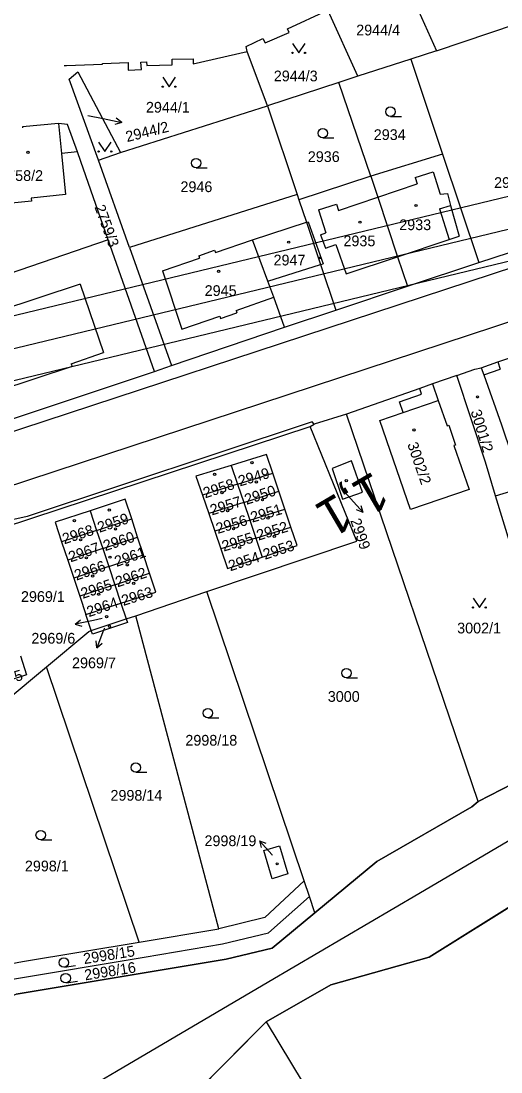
# Model space of a CAD drawing. Extents: x -738085 to -734306, y -1122197 to -1119753.
# Drawn here: x -735134.3 to -735058.2, y -1120249.4 to -1120082.8 of the extents above; entities that cross this region are included whole.
import ezdxf

# ---------------------------------------------------------------- set-up
doc = ezdxf.new("R2010")
doc.units = 0
for name, color, linetype in [('Hranice parcel', 7, 'Continuous'), ('Parcelní čísla', 7, 'Continuous'), ('Pop  PČ popisy', 7, 'Continuous'), ('SŽDC', 7, 'Continuous'), ('Vnitřní kresba', 7, 'Continuous'), ('Vrstva 1', 7, 'Continuous'), ('Vrstva 53', 7, 'Continuous'), ('Vrstva 7', 7, 'Continuous'), ('Značky budov', 7, 'Continuous'), ('Značky kultur', 7, 'Continuous')]:
    doc.layers.add(name, color=color, linetype=linetype)

msp = doc.modelspace()

# ---------------------------------------------------------------- linework, layer by layer
at = {"layer": 'Hranice parcel'}
for p, q in [((-735075.3, -1120072.25), (-735068.46, -1120087.54)), ((-735080.9, -1120091.58), (-735085.62, -1120081.24)), ((-735068.46, -1120087.54), (-735055.76, -1120083.29)), ((-735098.45, -1120087.65), (-735098.62, -1120086.89)), ((-735095.23, -1120096.29), (-735098.45, -1120087.65)), ((-735068.46, -1120087.54), (-735072.52, -1120088.87)), ((-735072.52, -1120088.87), (-735080.9, -1120091.58)), ((-735072.52, -1120088.87), (-735067.5, -1120103.92)), ((-735122.01, -1120104.88), (-735126.63, -1120092.04)), ((-735083.9, -1120092.59), (-735095.23, -1120096.29)), ((-735080.9, -1120091.58), (-735083.9, -1120092.59)), ((-735078.86, -1120107.44), (-735083.9, -1120092.59)), ((-735118.5, -1120103.67), (-735095.23, -1120096.29)), ((-735095.23, -1120096.29), (-735090.55, -1120110.32)), ((-735122.01, -1120104.88), (-735118.5, -1120103.67)), ((-735067.5, -1120103.92), (-735078.86, -1120107.44)), ((-735067.5, -1120103.92), (-735061.75, -1120121.13)), ((-735117.09, -1120118.74), (-735122.01, -1120104.88)), ((-735078.86, -1120107.44), (-735090.25, -1120111.21)), ((-735090.55, -1120110.32), (-735117.09, -1120118.74)), ((-735090.55, -1120110.32), (-735090.25, -1120111.21)), ((-735090.25, -1120111.21), (-735089.07, -1120114.75)), ((-735061.75, -1120121.13), (-735045.05, -1120115.6)), ((-735120.46, -1120117.53), (-735145, -1120125.91)), ((-735113.14, -1120138.39), (-735120.46, -1120117.53)), ((-735117.09, -1120118.74), (-735110.45, -1120137.46)), ((-735073.02, -1120124.89), (-735061.75, -1120121.13)), ((-735084.41, -1120128.69), (-735073.02, -1120124.89)), ((-735092.55, -1120131.37), (-735084.41, -1120128.69)), ((-735110.45, -1120137.46), (-735092.55, -1120131.37)), ((-735058.73, -1120136.86), (-735051.05, -1120134.3)), ((-735113.14, -1120138.39), (-735110.45, -1120137.46)), ((-735062.37, -1120138), (-735061.35, -1120137.8)), ((-735061.35, -1120137.8), (-735058.73, -1120136.86)), ((-735061.35, -1120137.8), (-735060.94, -1120138.94)), ((-735065.23, -1120139.01), (-735069.06, -1120140.35)), ((-735065.23, -1120139.01), (-735062.37, -1120138)), ((-735071.11, -1120141.07), (-735082.7, -1120145.17)), ((-735069.06, -1120140.35), (-735071.11, -1120141.07)), ((-735082.7, -1120145.17), (-735087.85, -1120146.72)), ((-735061.82, -1120206.57), (-735082.7, -1120145.17)), ((-735088.44, -1120147.09), (-735087.85, -1120146.72)), ((-735101, -1120153.28), (-735099.98, -1120156.28)), ((-735099.98, -1120156.28), (-735094.37, -1120154.53)), ((-735093.42, -1120157.38), (-735094.37, -1120154.53)), ((-735099.98, -1120156.28), (-735105.53, -1120158.02)), ((-735099.98, -1120156.28), (-735099, -1120159.14)), ((-735099, -1120159.14), (-735093.42, -1120157.38)), ((-735092.47, -1120160.22), (-735093.42, -1120157.38)), ((-735059.09, -1120158.11), (-735054.93, -1120156.86)), ((-735105.53, -1120158.02), (-735104.54, -1120160.89)), ((-735099, -1120159.14), (-735104.54, -1120160.89)), ((-735099, -1120159.14), (-735098.04, -1120161.98)), ((-735046.74, -1120198.74), (-735059.09, -1120158.11)), ((-735123.34, -1120160.47), (-735122.3, -1120163.59)), ((-735104.54, -1120160.89), (-735103.57, -1120163.72)), ((-735098.04, -1120161.98), (-735092.47, -1120160.22)), ((-735091.52, -1120163.05), (-735092.47, -1120160.22)), ((-735122.3, -1120163.59), (-735116.75, -1120161.76)), ((-735115.8, -1120164.64), (-735116.75, -1120161.76)), ((-735098.04, -1120161.98), (-735103.57, -1120163.72)), ((-735098.04, -1120161.98), (-735097.08, -1120164.8)), ((-735122.3, -1120163.59), (-735127.85, -1120165.42)), ((-735122.3, -1120163.59), (-735121.34, -1120166.47)), ((-735103.57, -1120163.72), (-735102.6, -1120166.53)), ((-735097.08, -1120164.8), (-735091.52, -1120163.05)), ((-735127.85, -1120165.42), (-735126.88, -1120168.31)), ((-735121.34, -1120166.47), (-735115.8, -1120164.64)), ((-735114.87, -1120167.48), (-735115.8, -1120164.64)), ((-735097.08, -1120164.8), (-735102.6, -1120166.53)), ((-735097.08, -1120164.8), (-735096.05, -1120167.82)), ((-735121.34, -1120166.47), (-735126.88, -1120168.31)), ((-735121.34, -1120166.47), (-735120.39, -1120169.32)), ((-735120.39, -1120169.32), (-735114.87, -1120167.48)), ((-735113.92, -1120170.36), (-735114.87, -1120167.48)), ((-735126.88, -1120168.31), (-735125.93, -1120171.17)), ((-735120.39, -1120169.32), (-735125.93, -1120171.17)), ((-735120.39, -1120169.32), (-735119.43, -1120172.19)), ((-735119.43, -1120172.19), (-735113.92, -1120170.36)), ((-735125.93, -1120171.17), (-735124.98, -1120174.02)), ((-735119.43, -1120172.19), (-735124.98, -1120174.02)), ((-735119.43, -1120172.19), (-735118.45, -1120175.13)), ((-735124.98, -1120174.02), (-735124.02, -1120176.91)), ((-735116.07, -1120177.1), (-735104.83, -1120173.29)), ((-735089.41, -1120219.11), (-735104.83, -1120173.29)), ((-735124.02, -1120176.91), (-735118.45, -1120175.13)), ((-735118.45, -1120175.13), (-735117.62, -1120177.62)), ((-735123.17, -1120179.46), (-735124.02, -1120176.91)), ((-735123.17, -1120179.46), (-735117.62, -1120177.62)), ((-735117.62, -1120177.62), (-735116.07, -1120177.1)), ((-735102.94, -1120226.73), (-735116.07, -1120177.1)), ((-735115.58, -1120228.85), (-735130.27, -1120185.19)), ((-735061.82, -1120206.57), (-735046.74, -1120198.74)), ((-735088.56, -1120221.64), (-735089.41, -1120219.11)), ((-735087.7, -1120224.18), (-735088.56, -1120221.64)), ((-735115.58, -1120228.85), (-735102.94, -1120226.73)), ((-735095.46, -1120241.5), (-735115.98, -1120262.16))]:
    msp.add_line(p, q, dxfattribs=at)
for points in [[(-735098.62, -1120086.89), (-735095.95, -1120085.59), (-735095.62, -1120086.32), (-735091.81, -1120084.64), (-735092.05, -1120084.09), (-735085.67, -1120081.14)], [(-735127.44, -1120089.91), (-735127.1, -1120089.9), (-735121.36, -1120089.67), (-735121.36, -1120089.55), (-735117.32, -1120089.42), (-735117.28, -1120090.61), (-735115.2, -1120090.54), (-735115.31, -1120089.35), (-735114.38, -1120089.32), (-735114.36, -1120089.91), (-735110.33, -1120089.76), (-735110.35, -1120088.91), (-735106.99, -1120088.82), (-735106.98, -1120089.62), (-735098.45, -1120087.65)], [(-735126.63, -1120092.04), (-735125.28, -1120090.88), (-735118.5, -1120103.67)], [(-735125.36, -1120103.6), (-735126.91, -1120099.24), (-735128.32, -1120099.07), (-735134.06, -1120099.62), (-735134.05, -1120099.76)], [(-734732.31, -1120124.29), (-734735.07, -1120127.22), (-734738.9, -1120128.4), (-734741.96, -1120128.37), (-734978.31, -1120104.89), (-734995.05, -1120103.5), (-735001.08, -1120103.64), (-735005.96, -1120104.65), (-735026.65, -1120111.99), (-735048.37, -1120119.26), (-735164.14, -1120157.32), (-735176.88, -1120160.91), (-735184.81, -1120162.43), (-735185.96, -1120162.53), (-735190.85, -1120162.98), (-735196.87, -1120162.75), (-735201.79, -1120161.48), (-735203.71, -1120160.98), (-735206.41, -1120159.5), (-735208.64, -1120157.56), (-735225.14, -1120141.26)], [(-735125.36, -1120103.6), (-735127.86, -1120103.82), (-735127.23, -1120110.36), (-735132.66, -1120110.91), (-735132.62, -1120111.38), (-735143.87, -1120112.49), (-735143.92, -1120112.06)], [(-735120.46, -1120117.53), (-735124.82, -1120105.12), (-735125.36, -1120103.6)], [(-735078.86, -1120107.44), (-735077.73, -1120110.77), (-735074.63, -1120120.2), (-735073.02, -1120124.89)], [(-735187.2, -1120177.07), (-735186.92, -1120175.94), (-735186.47, -1120174.12), (-735185.21, -1120172.48), (-735182.42, -1120171.13), (-735165.98, -1120166.38), (-735013.95, -1120116.34), (-735003.48, -1120113.01), (-735000.64, -1120112.19), (-735000, -1120112.13), (-734996.62, -1120111.83), (-734988.63, -1120112.11), (-734951.68, -1120115.51), (-734795.1, -1120131), (-734756.12, -1120134.99), (-734754.2, -1120137.32), (-734753.31, -1120137.78), (-734734.93, -1120139.52), (-734728.17, -1120141.08), (-734724.68, -1120142.84), (-734723.73, -1120143.69)], [(-735092.55, -1120131.37), (-735094.21, -1120126.62), (-735095.15, -1120124.07), (-735097.58, -1120117.5), (-735089.07, -1120114.75)], [(-735089.07, -1120114.75), (-735086.83, -1120121.44), (-735084.41, -1120128.69)], [(-735146.05, -1120149.39), (-735138.52, -1120146.86), (-735134.84, -1120145.62), (-735113.14, -1120138.39)], [(-735059.09, -1120158.11), (-735060.69, -1120152.78), (-735065.23, -1120139.01)], [(-735060.94, -1120138.94), (-735058.13, -1120146.86), (-735056.55, -1120151.54), (-735055.8, -1120154.02)], [(-735069.06, -1120140.35), (-735068.16, -1120142.97), (-735066.77, -1120147), (-735066.51, -1120146.92), (-735065.43, -1120150.06), (-735065.68, -1120150.15), (-735063.28, -1120157.09), (-735072.56, -1120160.27), (-735077.43, -1120146.17), (-735073.73, -1120144.9), (-735074.32, -1120143.19), (-735070.8, -1120141.98), (-735071.11, -1120141.07)], [(-735087.85, -1120146.72), (-735088.13, -1120146.35), (-735133.32, -1120161.4), (-735138.8, -1120162.57), (-735140.07, -1120160.51), (-735141.06, -1120160.29), (-735170.32, -1120169.83), (-735182.85, -1120173.37), (-735184.82, -1120176.33), (-735186.39, -1120176.82)], [(-735183.44, -1120181.78), (-735181.38, -1120177.73), (-735088.44, -1120147.09)], [(-735104.83, -1120173.29), (-735081.09, -1120165.3), (-735088.44, -1120147.09)], [(-735094.37, -1120154.53), (-735095.37, -1120151.55), (-735101, -1120153.28)], [(-735080.16, -1120157.54), (-735081.91, -1120152.53), (-735084.99, -1120153.78), (-735083.34, -1120158.65), (-735080.16, -1120157.54)], [(-735101, -1120153.28), (-735106.57, -1120155), (-735105.53, -1120158.02)], [(-735116.75, -1120161.76), (-735117.78, -1120158.64), (-735123.34, -1120160.47)], [(-735123.34, -1120160.47), (-735128.89, -1120162.29), (-735127.85, -1120165.42)], [(-735096.05, -1120167.82), (-735090.53, -1120166), (-735091.52, -1120163.05)], [(-735102.6, -1120166.53), (-735101.54, -1120169.62), (-735096.05, -1120167.82)], [(-735118.45, -1120175.13), (-735112.93, -1120173.36), (-735113.92, -1120170.36)], [(-735117.62, -1120177.62), (-735117.43, -1120178.2), (-735122.97, -1120180.05), (-735123.17, -1120179.46)], [(-735130.27, -1120185.19), (-735123.55, -1120179.59), (-735123.17, -1120179.46)], [(-735134.39, -1120183.46), (-735133.4, -1120186.47), (-735139.12, -1120188.35), (-735140.03, -1120185.46)], [(-735146.53, -1120196.94), (-735142.76, -1120195.6), (-735130.27, -1120185.19)], [(-735013.84, -1120194.15), (-735022.76, -1120201.89), (-735069.62, -1120231.25), (-735085.17, -1120235.61), (-735095.46, -1120241.5)], [(-735087.7, -1120224.18), (-735077.88, -1120216.09), (-735062.84, -1120207.4), (-735061.82, -1120206.57)], [(-735091.98, -1120218.04), (-735094.46, -1120218.82), (-735095.81, -1120214.32), (-735093.32, -1120213.58), (-735091.98, -1120218.04)], [(-735089.41, -1120219.11), (-735095.67, -1120224.96), (-735102.94, -1120226.73)], [(-735156.93, -1120242.93), (-735151.15, -1120240.68), (-735135.96, -1120234.75), (-735114.78, -1120231.21), (-735102.36, -1120229.14), (-735095.09, -1120227.37), (-735088.56, -1120221.64)], [(-735154.27, -1120245.72), (-735149.78, -1120242.77), (-735135.06, -1120237.08), (-735101.77, -1120231.55), (-735094.5, -1120229.78), (-735087.7, -1120224.18)], [(-735158.75, -1120241.02), (-735153.4, -1120238.91), (-735136.86, -1120232.42), (-735134.06, -1120231.94), (-735115.58, -1120228.85)], [(-735095.46, -1120241.5), (-735077.67, -1120270.9), (-735070.92, -1120286.13)]]:
    msp.add_lwpolyline(points, dxfattribs=at)
at = {"layer": 'Pop  PČ popisy'}
for p, q in [((-735123.68, -1120097.79), (-735121.26, -1120098.31)), ((-735121.26, -1120098.31), (-735118.33, -1120098.93)), ((-735118.33, -1120098.93), (-735119.41, -1120099.22)), ((-735118.33, -1120098.93), (-735119.2, -1120098.24)), ((-735083.01, -1120157.47), (-735082.07, -1120158.52)), ((-735082.07, -1120158.52), (-735080.06, -1120160.75)), ((-735080.06, -1120160.75), (-735081.1, -1120160.34)), ((-735080.06, -1120160.75), (-735080.36, -1120159.67)), ((-735125.71, -1120178.46), (-735124.84, -1120177.77)), ((-735121.45, -1120177.55), (-735122.78, -1120177.84)), ((-735122.78, -1120177.84), (-735125.71, -1120178.46)), ((-735125.71, -1120178.46), (-735124.63, -1120178.75)), ((-735121.19, -1120179.39), (-735122.27, -1120182.19)), ((-735121.08, -1120179.1), (-735121.19, -1120179.39)), ((-735122.27, -1120182.19), (-735122.37, -1120181.08)), ((-735122.27, -1120182.19), (-735121.44, -1120181.44)), ((-735094.51, -1120215), (-735096.52, -1120212.77)), ((-735096.52, -1120212.77), (-735095.48, -1120213.18)), ((-735096.52, -1120212.77), (-735096.22, -1120213.85)), ((-735094.42, -1120215.1), (-735094.51, -1120215))]:
    msp.add_line(p, q, dxfattribs=at)
at = {"layer": 'SŽDC'}
for p, q in [((-735046.74, -1120198.74), (-735061.82, -1120206.57)), ((-735069.62, -1120231.25), (-735022.76, -1120201.89)), ((-735062.84, -1120207.4), (-735077.88, -1120216.09)), ((-735061.82, -1120206.57), (-735062.84, -1120207.4)), ((-735077.88, -1120216.09), (-735087.7, -1120224.18)), ((-735087.7, -1120224.18), (-735094.5, -1120229.78)), ((-735094.5, -1120229.78), (-735101.77, -1120231.55)), ((-735101.77, -1120231.55), (-735135.06, -1120237.08)), ((-735085.17, -1120235.61), (-735069.62, -1120231.25)), ((-735095.46, -1120241.5), (-735085.17, -1120235.61)), ((-735115.98, -1120262.16), (-735095.46, -1120241.5))]:
    msp.add_line(p, q, dxfattribs=at)
at = {"layer": 'Vnitřní kresba'}
for p, q in [((-735128.32, -1120099.07), (-735127.86, -1120103.82)), ((-735071.82, -1120107.67), (-735068.98, -1120106.77)), ((-735071.82, -1120107.67), (-735071.5, -1120108.67)), ((-735068.98, -1120106.77), (-735067.86, -1120110.31)), ((-735077.73, -1120110.77), (-735071.5, -1120108.67)), ((-735083.95, -1120112.87), (-735077.73, -1120110.77)), ((-735067.86, -1120110.31), (-735066.7, -1120110.16)), ((-735066.7, -1120110.16), (-735066.23, -1120112.08)), ((-735087.15, -1120112.77), (-735084.27, -1120111.86)), ((-735087.15, -1120112.77), (-735086, -1120116.42)), ((-735084.27, -1120111.86), (-735083.95, -1120112.87)), ((-735067.97, -1120112.63), (-735066.23, -1120112.08)), ((-735067.97, -1120112.63), (-735066.46, -1120117.46)), ((-735066.23, -1120112.08), (-735064.86, -1120116.92)), ((-735089.07, -1120114.75), (-735088.77, -1120114.66)), ((-735088.77, -1120114.66), (-735086.42, -1120121.31)), ((-735103.47, -1120119.54), (-735097.58, -1120117.5)), ((-735086.85, -1120116.74), (-735086, -1120116.42)), ((-735086.85, -1120116.74), (-735086.06, -1120118.85)), ((-735074.63, -1120120.2), (-735066.46, -1120117.46)), ((-735066.46, -1120117.46), (-735064.86, -1120116.92)), ((-735106.12, -1120120.08), (-735103.6, -1120119.17)), ((-735103.6, -1120119.17), (-735103.47, -1120119.54)), ((-735086.06, -1120118.85), (-735084.42, -1120118.24)), ((-735084.42, -1120118.24), (-735082.78, -1120122.93)), ((-735111.88, -1120122.46), (-735106, -1120120.42)), ((-735106.12, -1120120.08), (-735106, -1120120.42)), ((-735082.78, -1120122.93), (-735074.63, -1120120.2)), ((-735111.88, -1120122.46), (-735108.81, -1120131.7)), ((-735095.15, -1120124.07), (-735086.83, -1120121.44)), ((-735086.83, -1120121.44), (-735086.42, -1120121.31)), ((-735124.92, -1120124.53), (-735154.29, -1120134.32)), ((-735124.92, -1120124.53), (-735121.2, -1120135.39)), ((-735100.19, -1120128.7), (-735094.21, -1120126.62)), ((-735102.67, -1120129.98), (-735100.06, -1120129.07)), ((-735100.19, -1120128.7), (-735100.06, -1120129.07)), ((-735108.81, -1120131.7), (-735102.8, -1120129.61)), ((-735102.8, -1120129.61), (-735102.67, -1120129.98)), ((-735126.35, -1120137.19), (-735121.2, -1120135.39)), ((-735126.2, -1120137.61), (-735150.75, -1120145.68)), ((-735126.35, -1120137.19), (-735126.2, -1120137.61)), ((-735058.73, -1120136.86), (-735058.34, -1120138.01)), ((-735060.94, -1120138.94), (-735058.34, -1120138.01)), ((-735073.73, -1120144.9), (-735068.16, -1120142.97))]:
    msp.add_line(p, q, dxfattribs=at)
at = {"layer": 'Vrstva 1'}
for points in [[(-734534.27, -1119984.39), (-735554.91, -1120230.88), (-735485.2, -1120519.57), (-734464.55, -1120273.08)], [(-734470.58, -1120269.4), (-735481.51, -1120513.53), (-735548.88, -1120234.56), (-734537.95, -1119990.43)], [(-734541.63, -1119996.45), (-735348.44, -1120191.3), (-735283.42, -1120460.56), (-734476.61, -1120265.71)]]:
    msp.add_lwpolyline(points, close=True, dxfattribs=at)
msp.add_lwpolyline([(-735048.63, -1120207.9), (-735071.26, -1120221.19), (-735095.02, -1120235.15), (-735119.18, -1120249.35), (-735123.66, -1120251.99), (-735132.32, -1120257.08), (-735139.95, -1120261.55), (-735146.73, -1120265.54), (-735150.83, -1120267.95), (-735166.13, -1120276.92), (-735184.2, -1120287.53), (-735210.89, -1120303.2), (-735238.62, -1120319.49), (-735239.7, -1120320.12), (-735247.26, -1120324.55), (-735256.8, -1120330.14), (-735273.62, -1120340.02), (-735285.77, -1120347.18), (-735296.08, -1120353.22), (-735304.06, -1120357.75)], dxfattribs=at)
at = {"layer": 'Vrstva 53'}
for points in [[(-734742.39, -1120198.31), (-734748.46, -1120195.41), (-734799.69, -1120183.7), (-734853.28, -1120170.95), (-734887.03, -1120164.91), (-734913.87, -1120162.91), (-734932.65, -1120163.73), (-734954.75, -1120168.56), (-734977.62, -1120176.17), (-734996.5, -1120184.52), (-735013.84, -1120194.15), (-735022.76, -1120201.89), (-735069.62, -1120231.25), (-735085.17, -1120235.61), (-735095.46, -1120241.5), (-735115.98, -1120262.16), (-735126.91, -1120271.38), (-735136.63, -1120262.8), (-735138.78, -1120260.72), (-735140.3, -1120259.25), (-735154.27, -1120245.72)], [(-735154.27, -1120245.72), (-735149.78, -1120242.77), (-735135.06, -1120237.08), (-735101.77, -1120231.55), (-735094.5, -1120229.78), (-735087.7, -1120224.18), (-735077.88, -1120216.09), (-735062.84, -1120207.4), (-735061.82, -1120206.57), (-735046.74, -1120198.74)]]:
    msp.add_lwpolyline(points, dxfattribs=at)
at = {"layer": 'Značky budov'}
for centre, radius in [((-735133.19, -1120103.64), 0.175), ((-735071.68, -1120112.09), 0.175), ((-735080.57, -1120114.73), 0.175), ((-735091.86, -1120117.9), 0.175), ((-735086.96, -1120120.41), 0.117), ((-735102.97, -1120122.52), 0.175), ((-735061.95, -1120142.42), 0.175), ((-735072.02, -1120147.66), 0.175), ((-735097.69, -1120152.84), 0.175), ((-735103.61, -1120154.68), 0.175), ((-735096.98, -1120155.9), 0.175), ((-735082.74, -1120155.71), 0.175), ((-735102.45, -1120157.61), 0.175), ((-735096.02, -1120158.73), 0.175), ((-735120.3, -1120160.36), 0.175), ((-735101.55, -1120160.47), 0.175), ((-735125.83, -1120162.03), 0.175), ((-735095.15, -1120161.63), 0.175), ((-735119.31, -1120163.35), 0.175), ((-735100.62, -1120163.34), 0.175), ((-735094.15, -1120164.53), 0.175), ((-735124.84, -1120165.08), 0.175), ((-735099.62, -1120166.3), 0.175), ((-735123.93, -1120167.93), 0.175), ((-735120.19, -1120167.82), 0.175), ((-735117.45, -1120169.05), 0.175), ((-735122.94, -1120170.82), 0.175), ((-735116.43, -1120171.97), 0.175), ((-735121.99, -1120173.7), 0.175), ((-735120.72, -1120177.25), 0.175), ((-735120.26, -1120178.78), 0.175), ((-735093.7, -1120216.43), 0.175)]:
    msp.add_circle(centre, radius, dxfattribs=at)
at = {"layer": 'Značky kultur'}
for p, q in [((-735075.75, -1120097.96), (-735074, -1120097.96)), ((-735086.47, -1120101.38), (-735084.72, -1120101.38)), ((-735106.54, -1120106.11), (-735104.79, -1120106.11)), ((-735082.72, -1120186.96), (-735080.97, -1120186.96)), ((-735104.67, -1120193.3), (-735102.92, -1120193.3)), ((-735116.1, -1120201.93), (-735114.35, -1120201.93)), ((-735131.16, -1120212.64), (-735129.41, -1120212.64)), ((-735127.38, -1120232.83), (-735125.65, -1120232.55)), ((-735127.09, -1120235.3), (-735125.36, -1120235.03))]:
    msp.add_line(p, q, dxfattribs=at)
for points in [[(-735091.27, -1120086.4), (-735090.27, -1120087.9), (-735089.27, -1120086.4)], [(-735111.83, -1120091.75), (-735110.83, -1120093.25), (-735109.83, -1120091.75)], [(-735121.98, -1120102.02), (-735120.98, -1120103.52), (-735119.98, -1120102.02)], [(-735062.65, -1120174.3), (-735061.65, -1120175.8), (-735060.65, -1120174.3)]]:
    msp.add_lwpolyline(points, dxfattribs=at)
for centre, radius in [((-735091.27, -1120087.9), 0.1), ((-735089.27, -1120087.9), 0.1), ((-735111.83, -1120093.25), 0.1), ((-735109.83, -1120093.25), 0.1), ((-735075.75, -1120097.21), 0.75), ((-735086.47, -1120100.63), 0.75), ((-735121.98, -1120103.52), 0.1), ((-735119.98, -1120103.52), 0.1), ((-735106.54, -1120105.36), 0.75), ((-735062.65, -1120175.8), 0.1), ((-735060.65, -1120175.8), 0.1), ((-735082.72, -1120186.21), 0.75), ((-735104.67, -1120192.55), 0.75), ((-735116.1, -1120201.18), 0.75), ((-735131.16, -1120211.89), 0.75), ((-735127.5, -1120232.09), 0.75), ((-735127.21, -1120234.56), 0.75)]:
    msp.add_circle(centre, radius, dxfattribs=at)

# ---------------------------------------------------------------- texts
at = {"layer": 'Parcelní čísla'}
for s, p in [('2944/4', (-735081.17, -1120085.12)), ('2944/3', (-735094.23, -1120092.4)), ('2944/1', (-735114.49, -1120097.36)), ('2934', (-735078.39, -1120101.7)), ('2936', (-735088.84, -1120105.19)), ('2758/2', (-735137.74, -1120108.19)), ('2932', (-735059.32, -1120109.3)), ('2946', (-735109.02, -1120109.96)), ('2933', (-735074.35, -1120115.99)), ('2935', (-735083.19, -1120118.54)), ('2947', (-735094.27, -1120121.58)), ('2945', (-735105.18, -1120126.42)), ('2969/1', (-735134.29, -1120174.92)), ('3002/1', (-735065.17, -1120179.91)), ('2969/6', (-735132.64, -1120181.53)), ('2969/7', (-735126.2, -1120185.43)), ('3000', (-735085.67, -1120190.76)), ('2998/18', (-735108.24, -1120197.7)), ('2998/14', (-735120.11, -1120206.43)), ('2998/19', (-735105.21, -1120213.63)), ('2998/1', (-735133.67, -1120217.63))]:
    msp.add_text(s, height=1.7, dxfattribs=at).set_placement(p)
for s, rotation, p in [('2944/2', 14, (-735117.47, -1120102.04)), ('2759/3', 290, (-735122.67, -1120112.31)), ('3001/2', 287, (-735063.06, -1120144.72)), ('3002/2', 289, (-735073.1, -1120149.92)), ('2949', 16, (-735099.6, -1120156.62)), ('2958', 18, (-735105.11, -1120158.51)), ('2950', 18, (-735098.55, -1120159.54)), ('2957', 17, (-735104.03, -1120161.22)), ('2951', 16, (-735097.64, -1120162.36)), ('2959', 18, (-735121.86, -1120163.96)), ('2956', 17, (-735103.1, -1120164.15)), ('2968', 18, (-735127.42, -1120165.79)), ('2952', 17, (-735096.66, -1120165.21)), ('2999', 289, (-735082.12, -1120162.01)), ('2960', 18, (-735120.94, -1120166.88)), ('2955', 17, (-735102.16, -1120166.95)), ('2967', 19, (-735126.42, -1120168.66)), ('2953', 18, (-735095.62, -1120168.24)), ('2961', 19, (-735119.14, -1120169.38)), ('2954', 18, (-735101.12, -1120170.07)), ('2966', 19, (-735125.5, -1120171.55)), ('2962', 19, (-735118.99, -1120172.63)), ('2965', 18, (-735124.5, -1120174.44)), ('2963', 17, (-735118.07, -1120175.56)), ('2964', 19, (-735123.53, -1120177.35)), ('2975', 18, (-735138.65, -1120188.78)), ('2998/15', 9, (-735124.27, -1120232.34)), ('2998/16', 9, (-735124.1, -1120234.92))]:
    msp.add_text(s, height=1.7, rotation=rotation, dxfattribs=at).set_placement(p)
at = {"layer": 'Vrstva 7'}
msp.add_text('1,1', height=6, rotation=210.44, dxfattribs=at).set_placement((-735078.4, -1120154.11))

doc.saveas('drawing.dxf')
